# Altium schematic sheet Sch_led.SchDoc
size Letter
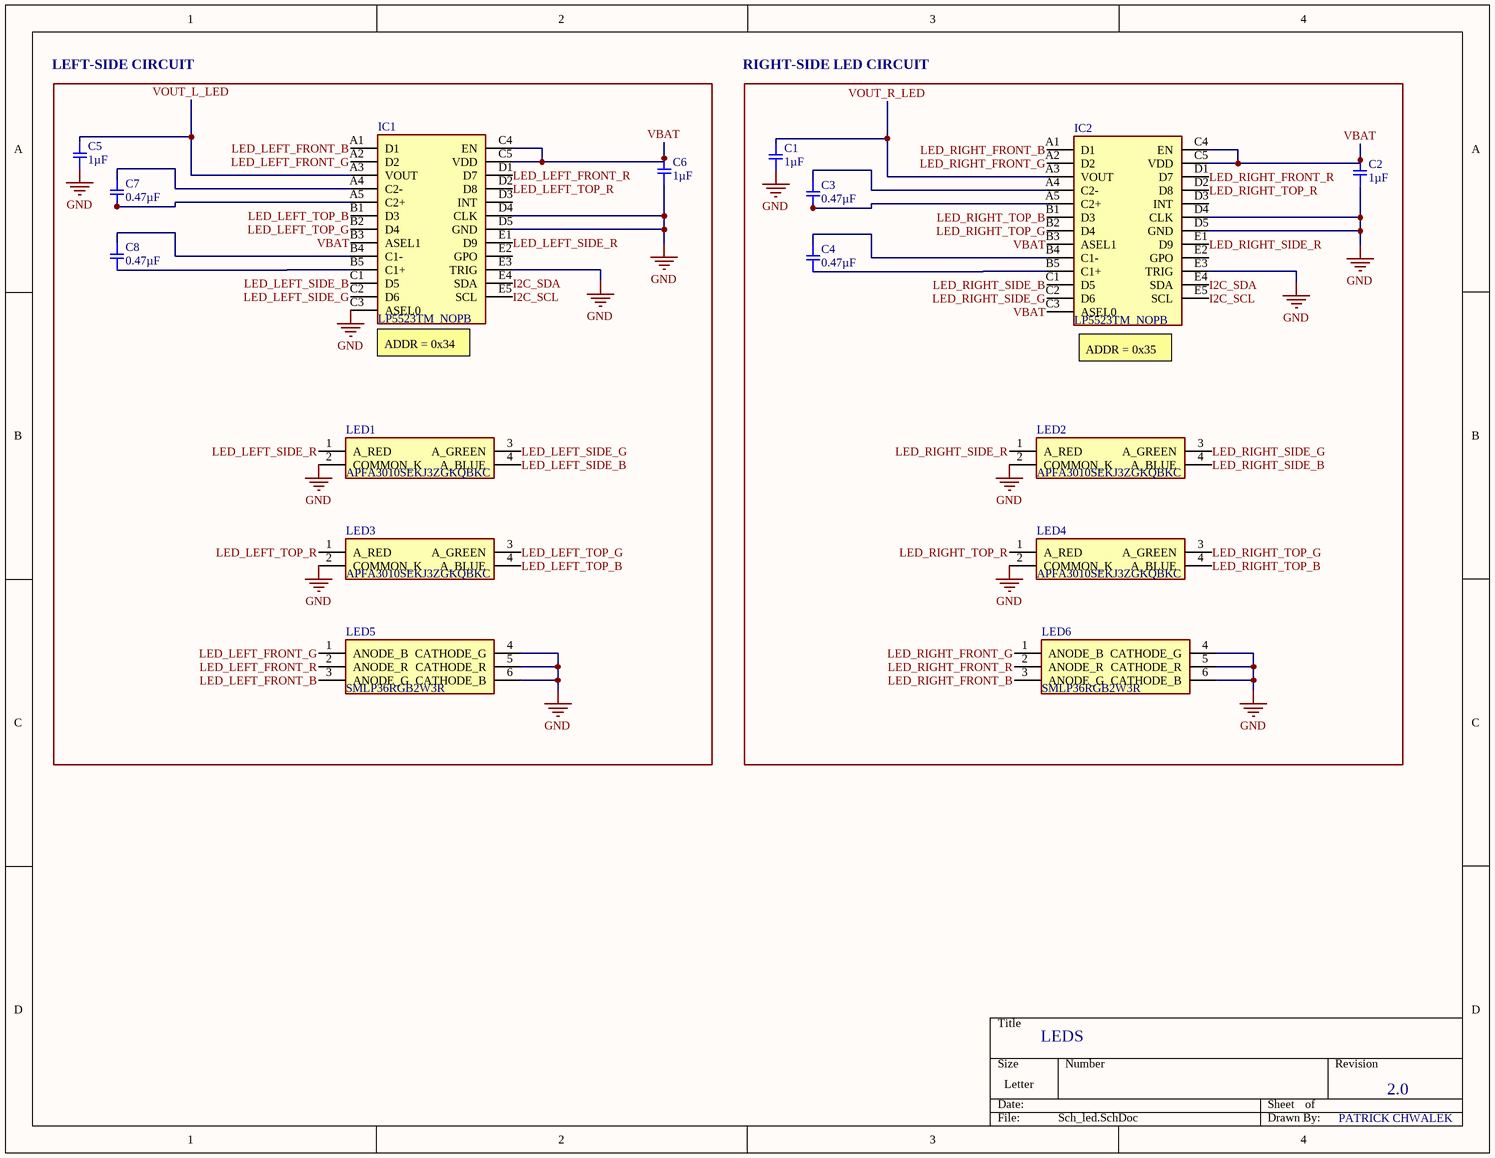
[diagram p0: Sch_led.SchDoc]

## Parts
C1  1µF  [0402R]
C2  1µF  [0402R]
C3  0.47µF  [0402R]
C4  0.47µF  [0402R]
C5  1µF  [0402R]
C6  1µF  [0402R]
C7  0.47µF  [0402R]
C8  0.47µF  [0402R]
IC1  LP5523TM_NOPB  [BGA25C40P5X5_226X226X68]
IC2  LP5523TM_NOPB  [BGA25C40P5X5_226X226X68]
LED1  APFA3010SEKJ3ZGKQBKC  [KPFA-3010RGBC-11]
LED2  APFA3010SEKJ3ZGKQBKC  [KPFA-3010RGBC-11]
LED3  APFA3010SEKJ3ZGKQBKC  [KPFA-3010RGBC-11]
LED4  APFA3010SEKJ3ZGKQBKC  [KPFA-3010RGBC-11]
LED5  SMLP36RGB2W3R  [ROHM-1510-(0604)]
LED6  SMLP36RGB2W3R  [ROHM-1510-(0604)]

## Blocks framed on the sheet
LEFT-SIDE CIRCUIT: C5-C8 IC1 LED1 LED3 LED5
RIGHT-SIDE LED CIRCUIT: C1-C4 IC2 LED2 LED4 LED6

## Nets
GND: C1.1 C2.1 C5.1 C6.1 IC1.C3(ASEL0) IC1.D4(CLK) IC1.D5(GND) IC1.E3(TRIG) IC2.D4(CLK) IC2.D5(GND) IC2.E3(TRIG) LED1.2(COMMON_K) LED2.2(COMMON_K) LED3.2(COMMON_K) LED4.2(COMMON_K) LED5.4(CATHODE_G) LED5.5(CATHODE_R) LED5.6(CATHODE_B) LED6.4(CATHODE_G) LED6.5(CATHODE_R) LED6.6(CATHODE_B)
I2C_SCL: IC1.E5(SCL) IC2.E5(SCL)
I2C_SDA: IC1.E4(SDA) IC2.E4(SDA)
LED_LEFT_FRONT_B: IC1.A1(D1) LED5.3(ANODE_G)
LED_LEFT_FRONT_G: IC1.A2(D2) LED5.1(ANODE_B)
LED_LEFT_FRONT_R: IC1.D1(D7) LED5.2(ANODE_R)
LED_LEFT_SIDE_B: IC1.C1(D5) LED1.4(A_BLUE)
LED_LEFT_SIDE_G: IC1.C2(D6) LED1.3(A_GREEN)
LED_LEFT_SIDE_R: IC1.E1(D9) LED1.1(A_RED)
LED_LEFT_TOP_B: IC1.B1(D3) LED3.4(A_BLUE)
LED_LEFT_TOP_G: IC1.B2(D4) LED3.3(A_GREEN)
LED_LEFT_TOP_R: IC1.D2(D8) LED3.1(A_RED)
LED_RIGHT_FRONT_B: IC2.A1(D1) LED6.3(ANODE_G)
LED_RIGHT_FRONT_G: IC2.A2(D2) LED6.1(ANODE_B)
LED_RIGHT_FRONT_R: IC2.D1(D7) LED6.2(ANODE_R)
LED_RIGHT_SIDE_B: IC2.C1(D5) LED2.4(A_BLUE)
LED_RIGHT_SIDE_G: IC2.C2(D6) LED2.3(A_GREEN)
LED_RIGHT_SIDE_R: IC2.E1(D9) LED2.1(A_RED)
LED_RIGHT_TOP_B: IC2.B1(D3) LED4.4(A_BLUE)
LED_RIGHT_TOP_G: IC2.B2(D4) LED4.3(A_GREEN)
LED_RIGHT_TOP_R: IC2.D2(D8) LED4.1(A_RED)
VBAT: C2.2 C6.2 IC1.B3(ASEL1) IC1.C4(EN) IC1.C5(VDD) IC2.B3(ASEL1) IC2.C3(ASEL0) IC2.C4(EN) IC2.C5(VDD)
VOUT_L_LED: C5.2 IC1.A3(VOUT)
VOUT_R_LED: C1.2 IC2.A3(VOUT)
NetC3_1: C3.1 IC2.A5(C2+)
NetC3_2: C3.2 IC2.A4(C2-)
NetC4_1: C4.1 IC2.B5(C1+)
NetC4_2: C4.2 IC2.B4(C1-)
NetC7_1: C7.1 IC1.A5(C2+)
NetC7_2: C7.2 IC1.A4(C2-)
NetC8_1: C8.1 IC1.B5(C1+)
NetC8_2: C8.2 IC1.B4(C1-)

Not connected (* = marked no-connect by the designer): IC1 D3(INT) E2(GPO); IC2 D3(INT) E2(GPO)

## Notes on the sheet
- (near IC1) ADDR = 0x34
- (near IC2) ADDR = 0x35
- LEDS
- 2.0
- PATRICK CHWALEK

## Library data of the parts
C1 C2 C5 C6 = GCM155C71A105KE38D: CAP CER 1UF 10V X7S 0402; Manufacturer: Murata Electronics North America; Factory Stock: 0; Unit Price (USD): 0.12; Minimum Quantity: 1; Tolerance: ±10%
C3 C4 C7 C8 = GCM155C71A105KE38D: CAP CER 0.47UF 10V X7S 0402; Manufacturer: Murata Electronics North America; Factory Stock: 0; Unit Price (USD): 0.12; Minimum Quantity: 1; Tolerance: ±10%
IC1 IC2 = LP5523TM_NOPB: Integrated Circuit; Manufacturer_Name: Texas Instruments; Manufacturer_Part_Number: LP5523TM/NOPB
LED1-LED4 = APFA3010SEKJ3ZGKQBKC: LED; Manufacturer_Name: Kingbright; Allied_Number: 70820377
LED5 LED6 = SMLP36RGB2W3R: LED; Manufacturer_Name: ROHM Semiconductor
